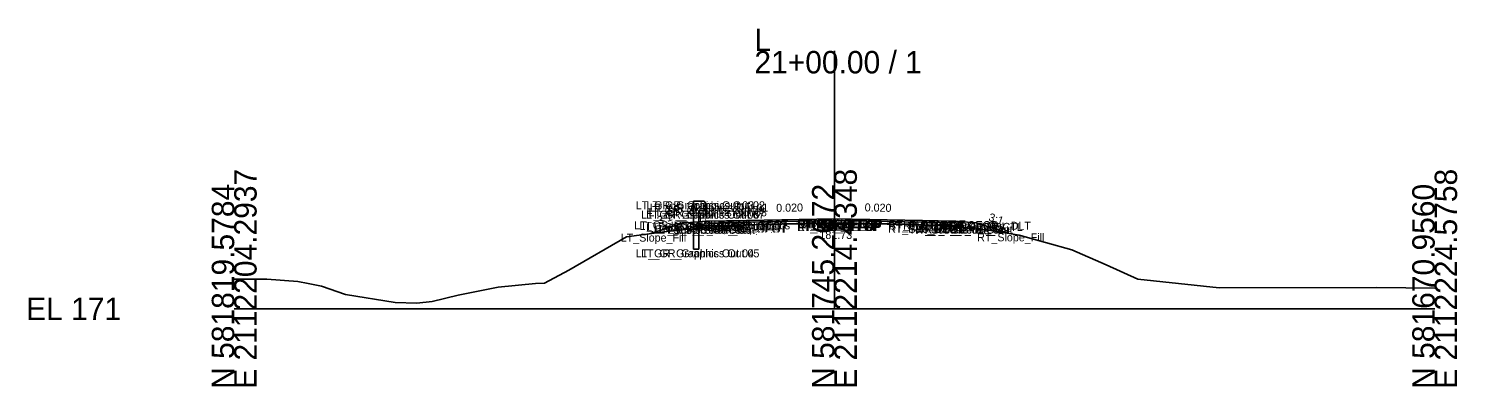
# Model space of a CAD drawing. Extents: x -26 to 3453, y -333 to 9539.
# Drawn here: x 974.3 to 1152.8, y 1990.3 to 2035 of the extents above; entities that cross this region are included whole.
import ezdxf

# ---------------------------------------------------------------- set-up
doc = ezdxf.new("R2010")
doc.units = 0
for name, color, linetype in [('Default', 7, 'Continuous'), ('Exist Cross Section Cell', 7, 'Continuous'), ('Exist XS Center Line Elevation Label', 7, 'Continuous'), ('Exist XS Ground Line', 7, 'Continuous'), ('Prop CMT Guardrail Graphics', 7, 'Continuous'), ('Prop CMT Pvmt Course 1', 7, 'Continuous'), ('Prop CMT Pvmt Course 2', 7, 'Continuous'), ('Prop CMT Pvmt Course 3', 7, 'Continuous'), ('Prop CMT Pvmt Surface', 7, 'Continuous'), ('Prop CMT Pvmt Surface Shoulder', 7, 'Continuous'), ('Prop CMT Shld Paved Course 1', 7, 'Continuous'), ('Prop CMT Shld Paved Course 2', 7, 'Continuous'), ('Prop CMT Shld Paved Course 3', 7, 'Continuous'), ('Prop CMT Slope Grass', 7, 'Continuous'), ('Prop CMT Subgrade Earthwork', 7, 'Continuous'), ('Prop XS SE Text', 7, 'Continuous'), ('Prop XS Side Slope Text', 7, 'Continuous'), ('Scratch_Level_0', 7, 'Continuous')]:
    doc.layers.add(name, color=color, linetype=linetype)

msp = doc.modelspace()

# ---------------------------------------------------------------- linework, layer by layer
at = {"layer": 'Exist Cross Section Cell'}
for p, q in [((1075, 2000), (1075, 2032.2)), ((1000, 2000), (1075, 2000)), ((1075, 2000), (1150, 2000))]:
    msp.add_line(p, q, dxfattribs=at)
at = {"layer": 'Exist XS Ground Line'}
for p, q in [((1058.86, 2010.14), (1065.34, 2010.54)), ((1065.34, 2010.54), (1071.88, 2010.68)), ((1071.88, 2010.68), (1074.77, 2010.73)), ((1074.77, 2010.73), (1081.85, 2010.61)), ((1081.85, 2010.61), (1084.9, 2010.57)), ((1084.9, 2010.57), (1088.78, 2010.32)), ((1088.78, 2010.32), (1094.05, 2009.87)), ((1041.83, 2004.81), (1049.03, 2008.98)), ((1049.03, 2008.98), (1054.07, 2009.66)), ((1054.07, 2009.66), (1058.86, 2010.14)), ((1094.05, 2009.87), (1098.07, 2009.19)), ((1098.07, 2009.19), (1104.66, 2007.37)), ((1104.66, 2007.37), (1108.93, 2005.48)), ((1108.93, 2005.48), (1112.91, 2003.7)), ((1000, 2003.7), (1004.08, 2003.7)), ((1004.08, 2003.7), (1007.96, 2003.39)), ((1007.96, 2003.39), (1009.26, 2003.14)), ((1009.26, 2003.14), (1010.9, 2002.84)), ((1032.99, 2002.71), (1037.63, 2003.16)), ((1037.63, 2003.16), (1038.77, 2003.19)), ((1038.77, 2003.19), (1041.83, 2004.81)), ((1112.91, 2003.7), (1123.08, 2002.63)), ((1010.9, 2002.84), (1013.9, 2001.79)), ((1013.9, 2001.79), (1020.1, 2000.78)), ((1024.74, 2000.9), (1028, 2001.72)), ((1028, 2001.72), (1032.99, 2002.71)), ((1123.08, 2002.63), (1142.75, 2002.68)), ((1142.75, 2002.68), (1150, 2002.58)), ((1020.1, 2000.78), (1022.82, 2000.71)), ((1022.82, 2000.71), (1024.74, 2000.9))]:
    msp.add_line(p, q, dxfattribs=at)
at = {"layer": 'Prop CMT Guardrail Graphics'}
for points in [[(1057.39, 2007.43), (1057.39, 2013.43)], [(1057.39, 2013.43), (1058.72, 2013.43), (1058.99, 2013.13)], [(1058.99, 2012.55), (1058.72, 2012.26), (1058.05, 2012.26)], [(1058.05, 2012.26), (1058.05, 2007.43)], [(1058.99, 2013.13), (1058.72, 2012.84)], [(1058.72, 2012.84), (1058.99, 2012.55)], [(1058.05, 2007.43), (1057.39, 2007.43)]]:
    msp.add_lwpolyline(points, dxfattribs=at)
at = {"layer": 'Prop CMT Pvmt Course 1'}
for points in [[(1075, 2011.25), (1064, 2011.03)], [(1064, 2010.82), (1075, 2011.04)], [(1064, 2011.03), (1064, 2010.82)], [(1075, 2011.04), (1075, 2011.25)], [(1075, 2011.25), (1086, 2011.03)], [(1075, 2011.04), (1075, 2011.25)], [(1086, 2010.82), (1075, 2011.04)], [(1086, 2011.03), (1086, 2010.82)]]:
    msp.add_lwpolyline(points, dxfattribs=at)
msp.add_lwpolyline([(1075, 2011.04), (1075, 2011.12), (1075, 2011.12), (1075, 2011.04)], close=True, dxfattribs=at)
msp.add_lwpolyline([(1075, 2011.04), (1075, 2011.12), (1075, 2011.12), (1075, 2011.04)], close=True, dxfattribs=at)
at = {"layer": 'Prop CMT Pvmt Course 2'}
for points in [[(1075, 2011.04), (1064, 2010.82)], [(1064, 2010.82), (1064, 2010.49)], [(1064, 2010.49), (1075, 2010.71)], [(1075, 2010.71), (1075, 2011.04)], [(1075, 2010.71), (1075, 2011.04)], [(1075, 2011.04), (1086, 2010.82)], [(1086, 2010.49), (1075, 2010.71)], [(1086, 2010.82), (1086, 2010.49)]]:
    msp.add_lwpolyline(points, dxfattribs=at)
at = {"layer": 'Prop CMT Pvmt Course 3'}
for points in [[(1075, 2010.71), (1064, 2010.49)], [(1064, 2010.49), (1075, 2010.71)], [(1064, 2010.49), (1064, 2010.49)], [(1075, 2010.71), (1075, 2010.71)], [(1075, 2010.71), (1086, 2010.49)], [(1086, 2010.49), (1075, 2010.71)], [(1075, 2010.71), (1075, 2010.71)], [(1086, 2010.49), (1086, 2010.49)]]:
    msp.add_lwpolyline(points, dxfattribs=at)
at = {"layer": 'Prop CMT Pvmt Surface'}
for points in [[(1075, 2011.25), (1064, 2011.03)], [(1075, 2011.25), (1086, 2011.03)]]:
    msp.add_lwpolyline(points, dxfattribs=at)
at = {"layer": 'Prop CMT Pvmt Surface Shoulder'}
for points in [[(1064, 2011.03), (1059, 2010.93)], [(1086, 2011.03), (1089.95, 2010.95)]]:
    msp.add_lwpolyline(points, dxfattribs=at)
at = {"layer": 'Prop CMT Shld Paved Course 1'}
for points in [[(1064, 2011.03), (1059, 2010.93), (1058.79, 2010.71)], [(1058.79, 2010.71), (1064, 2010.82)], [(1064, 2010.82), (1064, 2011.03)], [(1086, 2011.03), (1089.95, 2010.95), (1090.16, 2010.74)], [(1086, 2010.82), (1086, 2011.03)], [(1090.16, 2010.74), (1086, 2010.82)]]:
    msp.add_lwpolyline(points, dxfattribs=at)
at = {"layer": 'Prop CMT Shld Paved Course 2'}
for points in [[(1064, 2010.82), (1058.79, 2010.71), (1058.45, 2010.37)], [(1058.45, 2010.37), (1064, 2010.49)], [(1064, 2010.49), (1064, 2010.82)], [(1086, 2010.82), (1090.16, 2010.74), (1090.5, 2010.4)], [(1086, 2010.49), (1086, 2010.82)], [(1090.5, 2010.4), (1086, 2010.49)]]:
    msp.add_lwpolyline(points, dxfattribs=at)
at = {"layer": 'Prop CMT Shld Paved Course 3'}
for points in [[(1064, 2010.49), (1058.45, 2010.37)], [(1058.45, 2010.37), (1064, 2010.49)], [(1058.45, 2010.37), (1058.45, 2010.37), (1058.45, 2010.37)], [(1064, 2010.49), (1064, 2010.49)], [(1086, 2010.49), (1090.5, 2010.4)], [(1090.5, 2010.4), (1086, 2010.49)], [(1086, 2010.49), (1086, 2010.49)], [(1090.5, 2010.4), (1090.5, 2010.4), (1090.5, 2010.4)]]:
    msp.add_lwpolyline(points, dxfattribs=at)
at = {"layer": 'Prop CMT Slope Grass'}
for points in [[(1056, 2010.69), (1052.07, 2009.39)], [(1058.99, 2010.93), (1056, 2010.69)], [(1059, 2010.93), (1058.99, 2010.93)], [(1089.95, 2010.95), (1092.72, 2010.73), (1096.65, 2009.43)]]:
    msp.add_lwpolyline(points, dxfattribs=at)
at = {"layer": 'Prop CMT Subgrade Earthwork'}
for points in [[(1058.45, 2010.37), (1057.98, 2010.85)], [(1064, 2010.49), (1058.45, 2010.37)], [(1075, 2010.71), (1064, 2010.49)], [(1075, 2010.71), (1086, 2010.49)], [(1086, 2010.49), (1090.5, 2010.4)], [(1090.5, 2010.4), (1090.97, 2010.87)]]:
    msp.add_lwpolyline(points, dxfattribs=at)

# ---------------------------------------------------------------- texts
at = {"layer": 'Default'}
msp.add_text('-', height=0.0001, dxfattribs=at).set_placement((1000, 2000))
at = {"layer": 'Exist Cross Section Cell'}
for s, p in [('L', (1065, 2032.2)), ('21+00.00 / 1', (1065, 2029.4)), ('EL 171', (974, 1998.6))]:
    msp.add_text(s, height=2.8, dxfattribs=at).set_placement(p)
for s, p in [('E 2112204.2937', (1002.8, 1990)), ('E 2112214.4348', (1077.8, 1990)), ('E 2112224.5758', (1152.8, 1990)), ('N 581819.5784', (1000, 1990)), ('N 581745.2672', (1075, 1990)), ('N 581670.9560', (1150, 1990))]:
    msp.add_text(s, height=2.8, rotation=90, dxfattribs=at).set_placement(p)
at = {"layer": 'Exist XS Center Line Elevation Label'}
msp.add_text('181.73', height=1, dxfattribs=at).set_placement((1073.12, 2008.73))
at = {"layer": 'Prop XS SE Text'}
for rotation, p in [(1.1458, (1067.73, 2012.1)), (358.8542, (1078.77, 2012.17))]:
    msp.add_text('0.020', height=1, rotation=rotation, dxfattribs=at).set_placement(p)
at = {"layer": 'Prop XS Side Slope Text'}
for rotation, p in [(18.2629, (1053.05, 2010.5)), (341.7371, (1094.17, 2011.04))]:
    msp.add_text('3:1', height=1, rotation=rotation, dxfattribs=at).set_placement(p)
at = {"layer": 'Scratch_Level_0'}
for s, p in [('LT_GR_Graphics Out 03', (1050.17, 2012.43)), ('LT_GR_Graphics Out 06', (1050.83, 2011.26)), ('LT_GR_Graphics Out 07', (1051.48, 2011.26)), ('LT_GR_Graphics Out 09', (1051.49, 2011.84)), ('LT_GR_Graphics Out 02', (1051.52, 2012.43)), ('LT_GR_Graphics Out 08', (1051.76, 2011.55)), ('LT_GR_Graphics Out 01', (1051.94, 2012.13)), ('LT_GS_OS_GR_Face_Graphics', (1049.99, 2009.93)), ('LT_Sub_Trench_Out_DLT', (1050.63, 2009.85)), ('LT_GS_OS_CTL', (1051.46, 2009.69)), ('LT_Sub_Trench_Out', (1052.56, 2009.37)), ('LT_PS3_Shelf_Out', (1053.1, 2009.37)), ('LT_PS3_OEOP', (1054.23, 2009.37)), ('LT_PS2_OEOP', (1054.57, 2009.71)), ('LT_PS1_OEOP', (1054.91, 2009.93)), ('LT_PV2_OEOT', (1059.75, 2009.82)), ('LT_PV3_OEOT', (1059.75, 2009.49)), ('LT_Sub_OEOT', (1059.77, 2009.49)), ('LT_PV1_OEOT', (1059.87, 2010.03)), ('RT_PV2_OEEOP', (1070.33, 2010.04)), ('RT_PV3_OEEOP', (1070.33, 2009.71)), ('RT_Sub_OEEOP', (1070.36, 2009.71)), ('LT_PV2_OEEOP', (1070.39, 2010.04)), ('LT_PV3_OEEOP', (1070.39, 2009.71)), ('LT_Sub_OEEOP', (1070.42, 2009.71)), ('RT_PV1_OEEOP', (1070.45, 2010.12)), ('LT_PV1_OEEOP', (1070.51, 2010.12)), ('RT_PV2_IEEOP', (1070.71, 2010.04)), ('LT_PV2_IEEOP', (1070.77, 2010.04)), ('RT_PV1_IEEOP', (1070.83, 2010.12)), ('LT_PV1_IEEOP', (1070.89, 2010.12)), ('PV2_PGL', (1072.35, 2010.04)), ('PV1_PGL', (1072.47, 2010.25)), ('RT_PV2_OEOT', (1081.69, 2009.82)), ('RT_PV3_OEOT', (1081.69, 2009.49)), ('RT_Sub_OEOT', (1081.71, 2009.49)), ('RT_PV1_OEOT', (1081.81, 2010.03)), ('RT_Sub_Trench_Out_DLT', (1083.56, 2009.87)), ('RT_Sub_Trench_Out', (1084.55, 2009.4)), ('RT_PS3_Shelf_Out', (1085.1, 2009.4)), ('RT_PS1_OEOP', (1085.8, 2009.95)), ('RT_PS2_OEOP', (1085.89, 2009.74)), ('RT_PS3_OEOP', (1086.23, 2009.4)), ('RT_GS_OS_CTL', (1088.12, 2009.73)), ('LT_Slope_Fill', (1048.3, 2008.39)), ('RT_Slope_Fill', (1092.83, 2008.43)), ('LT_GR_Graphics Out 04', (1050.16, 2006.43)), ('LT_GR_Graphics Out 05', (1050.83, 2006.43))]:
    msp.add_text(s, height=1, dxfattribs=at).set_placement(p)

doc.saveas('drawing.dxf')
